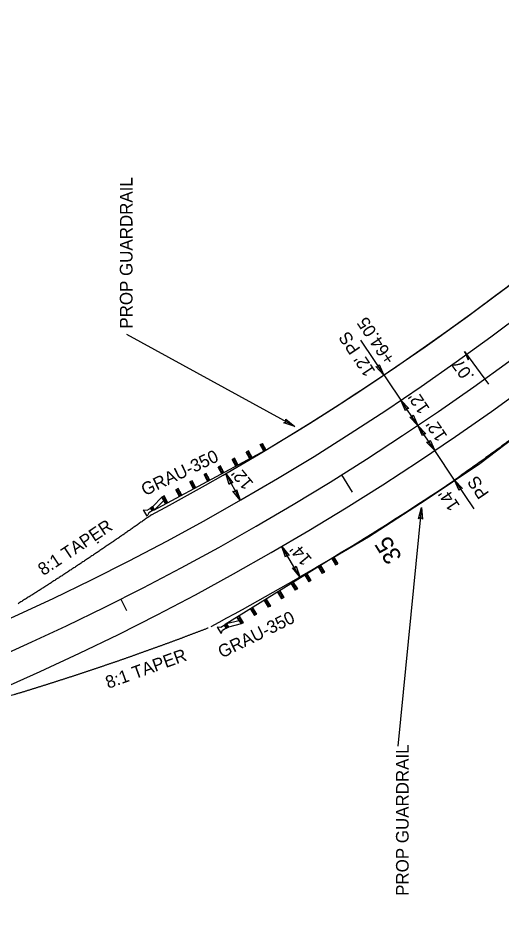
# Model space of a CAD drawing. Extents: x 2389694 to 2405615, y 547005 to 573532.
# Drawn here: x 2395308.3 to 2395499.4, y 553503.8 to 553860.1 of the extents above; entities that cross this region are included whole.
import ezdxf

# ---------------------------------------------------------------- set-up
doc = ezdxf.new("R2010")
doc.units = 0
for name, color, linetype in [('Prop Dimension', 7, 'Continuous'), ('Prop Dimension Text', 7, 'Continuous'), ('Prop DSN Text', 7, 'Continuous'), ('Prop EOT', 7, 'Continuous'), ('Prop GRAU 350 Approach CELL', 7, 'Continuous'), ('Prop Guardrail', 7, 'Continuous'), ('Prop Horizontal Alignment', 7, 'Continuous'), ('Prop Horizontal Alignment Curve and Spiral Data', 7, 'Continuous'), ('Prop Horizontal Alignment Tick Large', 7, 'Continuous'), ('Prop Horizontal Alignment Tick Small', 7, 'Continuous'), ('Prop Lane Lines', 7, 'Continuous'), ('Prop SBG', 7, 'Continuous'), ('Prop Super Arrow 1 Lane CELL', 7, 'Continuous'), ('Prop Superelevation Label', 7, 'Continuous')]:
    doc.layers.add(name, color=color, linetype=linetype)

msp = doc.modelspace()

# ---------------------------------------------------------------- linework, layer by layer
at = {"layer": 'Prop Dimension'}
for p, q in [((2395443.54, 553732.75), (2395459.39, 553709.17)), ((2395466.14, 553699.14), (2395459.44, 553709.09)), ((2395472.83, 553689.18), (2395466.14, 553699.14)), ((2395480.64, 553677.56), (2395472.83, 553689.18)), ((2395390.29, 553680.09), (2395396.04, 553669.56)), ((2395480.64, 553677.56), (2395488.28, 553666.19)), ((2395419.55, 553639.26), (2395412.51, 553651.36))]:
    msp.add_line(p, q, dxfattribs=at)
for points in [[(2395450.88, 553723.22), (2395452.75, 553719.05), (2395449.56, 553722.36), (2395450.54, 553722.33)], [(2395461.31, 553704.93), (2395459.44, 553709.09), (2395462.63, 553705.79), (2395461.65, 553705.82)], [(2395464.27, 553703.3), (2395466.14, 553699.14), (2395462.95, 553702.45), (2395463.93, 553702.41)], [(2395468, 553694.97), (2395466.14, 553699.14), (2395469.32, 553695.83), (2395468.34, 553695.86)], [(2395470.96, 553693.34), (2395472.83, 553689.18), (2395469.64, 553692.49), (2395470.63, 553692.46)], [(2395391.69, 553675.75), (2395390.29, 553680.09), (2395393.1, 553676.46), (2395392.12, 553676.59)], [(2395482.51, 553673.39), (2395480.64, 553677.56), (2395483.83, 553674.25), (2395482.85, 553674.28)], [(2395394.54, 553673.87), (2395396.04, 553669.56), (2395393.15, 553673.13), (2395394.13, 553673.02)], [(2395413.92, 553647.02), (2395412.51, 553651.36), (2395415.32, 553647.73), (2395414.35, 553647.86)], [(2395418.04, 553643.57), (2395419.55, 553639.26), (2395416.65, 553642.83), (2395417.63, 553642.71)]]:
    msp.add_lwpolyline(points, close=True, dxfattribs=at)
at = {"layer": 'Prop DSN Text'}
for p, q in [((2395417.62, 553698.76), (2395351.18, 553734.99)), ((2395458.38, 553572.41), (2395467.58, 553665.82))]:
    msp.add_line(p, q, dxfattribs=at)
for points in [[(2395414, 553701.55), (2395417.62, 553698.76), (2395413.25, 553700.17), (2395414.13, 553700.61)], [(2395466.41, 553662.29), (2395467.65, 553666.68), (2395467.97, 553662.1), (2395467.23, 553662.75)]]:
    msp.add_lwpolyline(points, close=True, dxfattribs=at)
at = {"layer": 'Prop EOT'}
msp.add_line((2395340.14, 553652.98), (2395339.58, 553652.67), dxfattribs=at)
for centre, radius, start, end in [((2394865.6, 554590.75), 1087, 256.52302, 12.63033), ((2394865.6, 554590.75), 1063, 256.52302, 12.63033), ((2394828.31, 550434.92), 3867, 59.69891, 109.59769), ((2394828.31, 550434.92), 3843, 59.69891, 123.9393), ((2394828.31, 550434.92), 3839, 59.69891, 123.9393), ((2394828.31, 550434.92), 3801, 59.69891, 123.9393), ((2394828.31, 550434.92), 3797, 59.69891, 123.9393), ((2394865.6, 554590.75), 1051, 298.11994, 326.25221), ((2394865.6, 554590.75), 1101, 298.12392, 303.94263)]:
    msp.add_arc(centre, radius, start, end, dxfattribs=at)
for points in [[(2395535.25, 553718.49), (2395534.53, 553717.92), (2395533.8, 553717.34), (2395533.08, 553716.76), (2395532.36, 553716.19), (2395531.64, 553715.62), (2395530.91, 553715.05), (2395530.19, 553714.48), (2395529.47, 553713.91), (2395528.74, 553713.34), (2395528.02, 553712.77), (2395527.3, 553712.2), (2395526.57, 553711.63), (2395525.84, 553711.06), (2395525.11, 553710.49), (2395524.39, 553709.92), (2395523.66, 553709.36), (2395522.93, 553708.79), (2395522.2, 553708.23), (2395521.47, 553707.66), (2395520.75, 553707.1), (2395520.02, 553706.54), (2395519.29, 553705.98), (2395518.56, 553705.41), (2395517.83, 553704.85), (2395517.09, 553704.29), (2395516.35, 553703.73), (2395515.62, 553703.17), (2395514.89, 553702.61), (2395514.16, 553702.05), (2395513.42, 553701.49), (2395512.69, 553700.94), (2395511.95, 553700.38), (2395511.22, 553699.83), (2395510.48, 553699.27), (2395509.75, 553698.72), (2395509, 553698.16), (2395508.27, 553697.6), (2395507.53, 553697.05), (2395506.79, 553696.5), (2395506.05, 553695.95), (2395505.31, 553695.4), (2395504.57, 553694.85), (2395503.83, 553694.3), (2395503.09, 553693.75), (2395502.35, 553693.2), (2395501.61, 553692.66), (2395500.86, 553692.1), (2395500.12, 553691.56), (2395499.38, 553691.01), (2395498.63, 553690.47), (2395497.89, 553689.92), (2395497.15, 553689.38), (2395496.4, 553688.83), (2395495.66, 553688.29), (2395494.91, 553687.75), (2395494.16, 553687.21), (2395493.42, 553686.67), (2395492.66, 553686.12), (2395491.92, 553685.58), (2395491.17, 553685.04), (2395490.42, 553684.51), (2395489.67, 553683.97), (2395488.92, 553683.43), (2395488.17, 553682.89), (2395487.42, 553682.36), (2395486.67, 553681.82), (2395485.92, 553681.29), (2395485.17, 553680.75), (2395484.41, 553680.22), (2395483.66, 553679.68), (2395482.9, 553679.15), (2395482.15, 553678.62), (2395480.64, 553677.56)], [(2395360.95, 553663.81), (2395360.26, 553663.32), (2395359.56, 553662.82), (2395358.87, 553662.33), (2395358.17, 553661.84), (2395357.47, 553661.35), (2395356.78, 553660.86), (2395356.08, 553660.37), (2395355.38, 553659.88), (2395354.68, 553659.39), (2395353.98, 553658.9), (2395353.28, 553658.41), (2395352.58, 553657.92), (2395351.88, 553657.43), (2395351.18, 553656.95), (2395350.48, 553656.46), (2395349.78, 553655.97), (2395349.08, 553655.49), (2395348.37, 553655), (2395347.67, 553654.52), (2395346.96, 553654.04), (2395346.26, 553653.55), (2395345.56, 553653.07), (2395344.85, 553652.59), (2395344.14, 553652.11), (2395343.44, 553651.63), (2395342.73, 553651.15), (2395342.02, 553650.67), (2395341.32, 553650.19), (2395340.61, 553649.71), (2395339.9, 553649.23), (2395339.19, 553648.75), (2395338.48, 553648.27), (2395337.77, 553647.8), (2395337.06, 553647.32), (2395336.35, 553646.84), (2395335.64, 553646.37), (2395334.93, 553645.89), (2395334.21, 553645.42), (2395333.5, 553644.95), (2395332.79, 553644.47), (2395332.07, 553644), (2395331.36, 553643.53), (2395330.65, 553643.06), (2395329.93, 553642.59), (2395329.21, 553642.12), (2395328.5, 553641.65), (2395327.78, 553641.18), (2395327.07, 553640.71), (2395326.35, 553640.24), (2395325.63, 553639.77), (2395324.91, 553639.31), (2395324.19, 553638.84), (2395323.47, 553638.37), (2395322.75, 553637.91), (2395322.03, 553637.44), (2395321.31, 553636.98), (2395320.59, 553636.51), (2395319.87, 553636.05), (2395319.15, 553635.59), (2395318.43, 553635.13), (2395317.71, 553634.66), (2395316.98, 553634.2), (2395316.26, 553633.74), (2395315.53, 553633.28), (2395314.81, 553632.82), (2395314.08, 553632.36), (2395313.36, 553631.9), (2395312.63, 553631.45), (2395311.91, 553630.99), (2395311.18, 553630.53), (2395310.45, 553630.08), (2395309.73, 553629.62), (2395308.27, 553628.71)], [(2395383.31, 553619.07), (2395382.79, 553618.87), (2395382.27, 553618.67), (2395381.75, 553618.47), (2395381.23, 553618.27), (2395380.71, 553618.07), (2395380.19, 553617.87), (2395379.67, 553617.67), (2395379.15, 553617.47), (2395378.63, 553617.27), (2395378.11, 553617.07), (2395377.59, 553616.88), (2395377.06, 553616.68), (2395376.54, 553616.48), (2395376.02, 553616.28), (2395375.5, 553616.09), (2395374.98, 553615.89), (2395374.46, 553615.7), (2395373.94, 553615.5), (2395373.41, 553615.3), (2395372.89, 553615.11), (2395372.37, 553614.91), (2395371.85, 553614.72), (2395371.33, 553614.52), (2395370.8, 553614.33), (2395370.28, 553614.14), (2395369.76, 553613.94), (2395369.24, 553613.75), (2395368.72, 553613.56), (2395368.19, 553613.36), (2395367.67, 553613.17), (2395367.15, 553612.98), (2395366.63, 553612.79), (2395366.1, 553612.6), (2395365.58, 553612.4), (2395365.06, 553612.21), (2395364.54, 553612.02), (2395364.01, 553611.83), (2395363.49, 553611.64), (2395362.97, 553611.45), (2395362.44, 553611.26), (2395361.92, 553611.07), (2395361.4, 553610.88), (2395360.87, 553610.69), (2395360.35, 553610.51), (2395359.83, 553610.32), (2395359.3, 553610.13), (2395358.78, 553609.94), (2395358.26, 553609.75), (2395357.73, 553609.57), (2395357.21, 553609.38), (2395356.69, 553609.19), (2395356.16, 553609.01), (2395355.64, 553608.82), (2395355.11, 553608.64), (2395354.59, 553608.45), (2395354.07, 553608.26), (2395353.54, 553608.08), (2395353.02, 553607.89), (2395352.49, 553607.71), (2395351.97, 553607.53), (2395351.44, 553607.34), (2395350.92, 553607.16), (2395350.4, 553606.98), (2395349.87, 553606.79), (2395349.35, 553606.61), (2395348.82, 553606.43), (2395348.3, 553606.24), (2395347.77, 553606.06), (2395347.25, 553605.88), (2395346.72, 553605.7), (2395346.2, 553605.52), (2395345.67, 553605.34), (2395345.15, 553605.16), (2395344.62, 553604.98)], [(2395344.62, 553604.98), (2395344.1, 553604.8), (2395343.57, 553604.62), (2395343.05, 553604.44), (2395342.52, 553604.26), (2395342, 553604.08), (2395341.47, 553603.9), (2395340.94, 553603.72), (2395340.42, 553603.55), (2395339.89, 553603.37), (2395339.37, 553603.19), (2395338.84, 553603.01), (2395338.32, 553602.84), (2395337.79, 553602.66), (2395337.26, 553602.48), (2395336.74, 553602.31), (2395336.21, 553602.13), (2395335.69, 553601.96), (2395335.16, 553601.78), (2395334.63, 553601.61), (2395334.11, 553601.43), (2395333.58, 553601.26), (2395333.05, 553601.08), (2395332.53, 553600.91), (2395332, 553600.74), (2395331.47, 553600.56), (2395330.95, 553600.39), (2395330.42, 553600.22), (2395329.89, 553600.04), (2395329.37, 553599.87), (2395328.84, 553599.7), (2395328.31, 553599.53), (2395327.79, 553599.36), (2395327.26, 553599.19), (2395326.73, 553599.02), (2395326.2, 553598.85), (2395325.68, 553598.67), (2395325.15, 553598.51), (2395324.62, 553598.34), (2395324.1, 553598.17), (2395323.57, 553598), (2395323.04, 553597.83), (2395322.51, 553597.66), (2395321.99, 553597.49), (2395321.46, 553597.32), (2395320.93, 553597.16), (2395320.4, 553596.99), (2395319.87, 553596.82), (2395319.35, 553596.65), (2395318.82, 553596.49), (2395318.29, 553596.32), (2395317.76, 553596.16), (2395317.23, 553595.99), (2395316.71, 553595.82), (2395316.18, 553595.66), (2395315.65, 553595.49), (2395315.12, 553595.33), (2395314.59, 553595.17), (2395314.06, 553595), (2395313.54, 553594.84), (2395313.01, 553594.67), (2395312.48, 553594.51), (2395311.95, 553594.35), (2395311.42, 553594.19), (2395310.89, 553594.02), (2395310.36, 553593.86), (2395309.84, 553593.7), (2395309.31, 553593.54), (2395308.78, 553593.38), (2395308.25, 553593.22), (2395307.72, 553593.06), (2395307.19, 553592.89), (2395306.66, 553592.73), (2395305.6, 553592.42)]]:
    msp.add_spline(points, degree=3, dxfattribs=at)
at = {"layer": 'Prop GRAU 350 Approach CELL'}
for p, q in [((2395403.91, 553691.54), (2395404.78, 553692.04)), ((2395405.38, 553688.93), (2395403.91, 553691.54)), ((2395405.52, 553690.73), (2395403.91, 553691.54)), ((2395404.78, 553692.04), (2395404.64, 553690.24)), ((2395405.52, 553690.73), (2395404.64, 553690.24)), ((2395404.64, 553690.24), (2395406.25, 553689.42)), ((2395406.25, 553689.42), (2395404.78, 553692.04)), ((2395405.38, 553688.93), (2395405.52, 553690.73)), ((2395405.81, 553689.18), (2395361.74, 553665.54)), ((2395399.28, 553689.08), (2395398.4, 553688.6)), ((2395399.82, 553685.96), (2395398.4, 553688.6)), ((2395398.4, 553688.6), (2395399.99, 553687.76)), ((2395399.11, 553687.28), (2395399.28, 553689.08)), ((2395399.99, 553687.76), (2395399.11, 553687.28)), ((2395399.82, 553685.96), (2395399.11, 553687.28)), ((2395399.11, 553687.28), (2395400.7, 553686.43)), ((2395400.7, 553686.43), (2395399.28, 553689.08)), ((2395399.99, 553687.76), (2395399.82, 553685.96)), ((2395400.7, 553686.43), (2395399.82, 553685.96)), ((2395406.25, 553689.42), (2395405.38, 553688.93)), ((2395388.16, 553683.16), (2395387.27, 553682.69)), ((2395387.99, 553681.35), (2395388.16, 553683.16)), ((2395389.6, 553680.48), (2395388.16, 553683.16)), ((2395393.71, 553686.15), (2395392.82, 553685.67)), ((2395394.27, 553682.98), (2395392.82, 553685.67)), ((2395392.82, 553685.67), (2395394.43, 553684.8)), ((2395393.55, 553684.33), (2395393.71, 553686.15)), ((2395394.43, 553684.8), (2395393.55, 553684.33)), ((2395395.15, 553683.46), (2395393.55, 553684.33)), ((2395395.15, 553683.46), (2395393.71, 553686.15)), ((2395394.43, 553684.8), (2395394.27, 553682.98)), ((2395382.61, 553680.18), (2395381.73, 553679.7)), ((2395383.16, 553677.03), (2395381.73, 553679.7)), ((2395381.73, 553679.7), (2395383.33, 553678.84)), ((2395382.44, 553678.36), (2395382.61, 553680.18)), ((2395384.04, 553677.5), (2395382.61, 553680.18)), ((2395388.71, 553680), (2395387.27, 553682.69)), ((2395387.27, 553682.69), (2395388.87, 553681.82)), ((2395388.87, 553681.82), (2395387.99, 553681.35)), ((2395389.6, 553680.48), (2395387.99, 553681.35)), ((2395388.87, 553681.82), (2395388.71, 553680)), ((2395377.01, 553677.29), (2395376.13, 553676.81)), ((2395377.61, 553674.05), (2395376.13, 553676.81)), ((2395376.13, 553676.81), (2395377.75, 553675.9)), ((2395376.87, 553675.43), (2395377.01, 553677.29)), ((2395377.75, 553675.9), (2395376.87, 553675.43)), ((2395378.49, 553674.52), (2395377.01, 553677.29)), ((2395377.75, 553675.9), (2395377.61, 553674.05)), ((2395383.33, 553678.84), (2395382.44, 553678.36)), ((2395384.04, 553677.5), (2395382.44, 553678.36)), ((2395383.33, 553678.84), (2395383.16, 553677.03)), ((2395384.04, 553677.5), (2395383.16, 553677.03)), ((2395371.52, 553674.19), (2395370.64, 553673.71)), ((2395372.06, 553671.07), (2395370.64, 553673.71)), ((2395370.64, 553673.71), (2395372.23, 553672.87)), ((2395371.35, 553672.39), (2395371.52, 553674.19)), ((2395372.23, 553672.87), (2395371.35, 553672.39)), ((2395372.94, 553671.54), (2395371.35, 553672.39)), ((2395372.94, 553671.54), (2395371.52, 553674.19)), ((2395372.23, 553672.87), (2395372.06, 553671.07)), ((2395378.49, 553674.52), (2395376.87, 553675.43)), ((2395365.05, 553670.79), (2395361.47, 553667.1)), ((2395365.78, 553669.44), (2395362.18, 553665.78)), ((2395365.94, 553671.27), (2395365.05, 553670.79)), ((2395366.5, 553668.09), (2395365.05, 553670.79)), ((2395365.05, 553670.79), (2395366.66, 553669.92)), ((2395365.78, 553669.44), (2395365.94, 553671.27)), ((2395366.66, 553669.92), (2395365.78, 553669.44)), ((2395367.38, 553668.57), (2395365.78, 553669.44)), ((2395367.38, 553668.57), (2395365.94, 553671.27)), ((2395366.66, 553669.92), (2395366.5, 553668.09)), ((2395359.29, 553663.27), (2395357.85, 553665.83)), ((2395357.85, 553665.83), (2395359.3, 553665.66)), ((2395359.3, 553665.66), (2395361.08, 553666.66)), ((2395361.68, 553665.59), (2395359.89, 553664.59)), ((2395361.47, 553667.1), (2395360.59, 553666.63)), ((2395361.3, 553665.3), (2395360.59, 553666.63)), ((2395360.59, 553666.63), (2395362.18, 553665.78)), ((2395361.47, 553667.1), (2395361.03, 553666.86)), ((2395361.08, 553666.66), (2395361.38, 553666.12)), ((2395361.3, 553665.3), (2395361.47, 553667.1)), ((2395361.38, 553666.12), (2395361.68, 553665.59)), ((2395362.18, 553665.78), (2395361.47, 553667.1)), ((2395359.89, 553664.59), (2395359.29, 553663.27)), ((2395432.6, 553646.82), (2395390.12, 553620.43)), ((2395427.67, 553643.76), (2395426.82, 553643.23)), ((2395427.61, 553641.96), (2395427.67, 553643.76)), ((2395427.67, 553643.76), (2395429.25, 553641.21)), ((2395433.03, 553647.08), (2395432.17, 553646.57)), ((2395432.17, 553646.57), (2395433.7, 553643.99)), ((2395432.17, 553646.57), (2395433.79, 553645.79)), ((2395432.93, 553645.28), (2395433.03, 553647.08)), ((2395433.79, 553645.79), (2395432.93, 553645.28)), ((2395434.56, 553644.5), (2395432.93, 553645.28)), ((2395433.03, 553647.08), (2395434.56, 553644.5)), ((2395433.79, 553645.79), (2395433.7, 553643.99)), ((2395433.7, 553643.99), (2395434.56, 553644.5)), ((2395422.32, 553640.44), (2395422.27, 553638.61)), ((2395422.32, 553640.44), (2395423.93, 553637.84)), ((2395426.82, 553643.23), (2395428.4, 553640.69)), ((2395426.82, 553643.23), (2395427.61, 553641.96)), ((2395428.46, 553642.49), (2395426.82, 553643.23)), ((2395428.46, 553642.49), (2395427.61, 553641.96)), ((2395427.61, 553641.96), (2395429.25, 553641.21)), ((2395428.4, 553640.69), (2395428.46, 553642.49)), ((2395429.25, 553641.21), (2395428.4, 553640.69)), ((2395416.12, 553636.58), (2395417.72, 553633.99)), ((2395417.77, 553635.81), (2395416.12, 553636.58)), ((2395416.96, 553637.11), (2395416.92, 553635.29)), ((2395416.96, 553637.11), (2395418.57, 553634.52)), ((2395421.47, 553639.91), (2395423.08, 553637.32)), ((2395423.12, 553639.14), (2395421.47, 553639.91)), ((2395423.12, 553639.14), (2395422.27, 553638.61)), ((2395422.27, 553638.61), (2395423.93, 553637.84)), ((2395423.08, 553637.32), (2395423.12, 553639.14)), ((2395423.93, 553637.84), (2395423.08, 553637.32)), ((2395411.61, 553633.78), (2395410.76, 553633.26)), ((2395410.76, 553633.26), (2395412.37, 553630.68)), ((2395412.41, 553632.49), (2395410.76, 553633.26)), ((2395411.61, 553633.78), (2395411.56, 553631.97)), ((2395411.61, 553633.78), (2395413.22, 553631.21)), ((2395417.77, 553635.81), (2395416.92, 553635.29)), ((2395416.92, 553635.29), (2395418.57, 553634.52)), ((2395417.72, 553633.99), (2395417.77, 553635.81)), ((2395418.57, 553634.52), (2395417.72, 553633.99)), ((2395405.41, 553629.93), (2395407.07, 553627.27)), ((2395407.09, 553629.13), (2395405.41, 553629.93)), ((2395406.26, 553630.46), (2395406.24, 553628.6)), ((2395406.26, 553630.46), (2395407.92, 553627.79)), ((2395412.41, 553632.49), (2395411.56, 553631.97)), ((2395411.56, 553631.97), (2395413.22, 553631.21)), ((2395412.37, 553630.68), (2395412.41, 553632.49)), ((2395413.22, 553631.21), (2395412.37, 553630.68)), ((2395400.06, 553626.6), (2395401.64, 553624.06)), ((2395401.7, 553625.86), (2395400.06, 553626.6)), ((2395400.91, 553627.13), (2395400.85, 553625.33)), ((2395401.7, 553625.86), (2395400.85, 553625.33)), ((2395400.91, 553627.13), (2395402.49, 553624.59)), ((2395401.64, 553624.06), (2395401.7, 553625.86)), ((2395407.09, 553629.13), (2395406.24, 553628.6)), ((2395406.24, 553628.6), (2395407.92, 553627.79)), ((2395407.07, 553627.27), (2395407.09, 553629.13)), ((2395407.92, 553627.79), (2395407.07, 553627.27)), ((2395394.71, 553623.28), (2395396.32, 553620.68)), ((2395396.37, 553622.51), (2395394.71, 553623.28)), ((2395395.56, 553623.81), (2395395.52, 553621.98)), ((2395396.37, 553622.51), (2395395.52, 553621.98)), ((2395395.56, 553623.81), (2395397.17, 553621.2)), ((2395396.32, 553620.68), (2395396.37, 553622.51)), ((2395400.85, 553625.33), (2395402.49, 553624.59)), ((2395402.49, 553624.59), (2395401.64, 553624.06)), ((2395388.37, 553619.3), (2395386.92, 553619.44)), ((2395386.92, 553619.44), (2395388.43, 553616.91)), ((2395390.13, 553620.35), (2395388.37, 553619.3)), ((2395389, 553618.25), (2395390.76, 553619.3)), ((2395389.69, 553620.16), (2395390.49, 553618.89)), ((2395389.69, 553620.16), (2395391.34, 553619.42)), ((2395390.45, 553619.82), (2395390.13, 553620.35)), ((2395390.76, 553619.3), (2395390.45, 553619.82)), ((2395390.49, 553618.89), (2395390.54, 553620.69)), ((2395391.34, 553619.42), (2395390.49, 553618.89)), ((2395395.52, 553621.98), (2395390.54, 553620.69)), ((2395390.54, 553620.69), (2395391.34, 553619.42)), ((2395391.34, 553619.42), (2395390.91, 553619.15)), ((2395396.32, 553620.68), (2395391.34, 553619.42)), ((2395395.52, 553621.98), (2395397.17, 553621.2)), ((2395397.17, 553621.2), (2395396.32, 553620.68)), ((2395388.43, 553616.91), (2395389, 553618.25))]:
    msp.add_line(p, q, dxfattribs=at)
at = {"layer": 'Prop Guardrail'}
for p, q in [((2395490.7, 553684.14), (2395519.05, 553705.77)), ((2395469.44, 553669.82), (2395490.7, 553684.14)), ((2395446.71, 553655.08), (2395469.44, 553669.82)), ((2395433.03, 553647.08), (2395446.71, 553655.08))]:
    msp.add_line(p, q, dxfattribs=at)
msp.add_arc((2394865.6, 554590.75), 1051, 300.92972, 324.79608, dxfattribs=at)
at = {"layer": 'Prop Horizontal Alignment'}
for centre, radius, start, end in [((2394865.6, 554590.75), 1075, 256.52302, 12.63033), ((2394828.31, 550434.92), 3820, 59.69891, 123.9393)]:
    msp.add_arc(centre, radius, start, end, dxfattribs=at)
at = {"layer": 'Prop Horizontal Alignment Tick Large'}
msp.add_line((2395436, 553679.56), (2395440.24, 553672.78), dxfattribs=at)
at = {"layer": 'Prop Horizontal Alignment Tick Small'}
msp.add_line((2395348.89, 553630.52), (2395351.14, 553626.05), dxfattribs=at)
at = {"layer": 'Prop Lane Lines'}
for radius, end in [(3855, 123.9393), (3785, 123.9393), (3773, 88.86914)]:
    msp.add_arc((2394828.31, 550434.92), radius, 59.69891, end, dxfattribs=at)
at = {"layer": 'Prop SBG'}
msp.add_arc((2394865.6, 554590.75), 1051, 301.77355, 326.29315, dxfattribs=at)
at = {"layer": 'Prop Super Arrow 1 Lane CELL'}
msp.add_line((2395484.55, 553728.28), (2395494.01, 553715.38), dxfattribs=at)
msp.add_lwpolyline([(2395484.55, 553728.28), (2395485.97, 553724.99), (2395486.29, 553725.9)], close=True, dxfattribs=at)

# ---------------------------------------------------------------- texts
at = {"layer": 'Prop Dimension Text'}
for s, rotation, p in [('+64.05', 123.9118, (2395457.44, 553725.36)), ("12' PS", 123.9111, (2395449.57, 553720.55)), ("12'", 123.9118, (2395471.02, 553705.78)), ("12'", 123.9118, (2395478.01, 553694.91)), ("12'", 129.8095, (2395401.5, 553676.31)), ('PS', 123.9111, (2395494.5, 553672.27)), ("14'", 123.9111, (2395482.93, 553667.44)), ("14'", 129.9082, (2395424.61, 553646.29))]:
    msp.add_text(s, height=5, rotation=rotation, dxfattribs=at).set_placement(p)
at = {"layer": 'Prop DSN Text'}
for s, rotation, p in [('PROP GUARDRAIL', 90, (2395353.47, 553737.37)), ('GRAU-350', 25.494, (2395358.4, 553671.15)), ('8:1 TAPER', 33.7989, (2395318.26, 553639.58)), ('GRAU-350', 26.374, (2395388.77, 553607.03)), ('8:1 TAPER', 19.8958, (2395343.89, 553595.03)), ('PROP GUARDRAIL', 90, (2395462.53, 553513.27))]:
    msp.add_text(s, height=5, rotation=rotation, dxfattribs=at).set_placement(p)
at = {"layer": 'Prop Horizontal Alignment Curve and Spiral Data'}
msp.add_text('35', height=7, rotation=122.0461, dxfattribs=at).set_placement((2395460.16, 553647.2))
at = {"layer": 'Prop Superelevation Label'}
msp.add_text('.07', height=5, rotation=126.2399, dxfattribs=at).set_placement((2395488.66, 553718.55))

doc.saveas('drawing.dxf')
